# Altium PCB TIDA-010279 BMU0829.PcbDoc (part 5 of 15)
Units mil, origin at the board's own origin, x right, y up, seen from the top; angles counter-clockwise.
Board outline 11269.69 x 4438.98 mil, 4 copper layers (Top Layer, Signal Layer 1, Signal Layer 2, Bottom Layer), stack 61.6 mil thick; 1494 components, 725 nets, 3766 pads, 2728 vias.
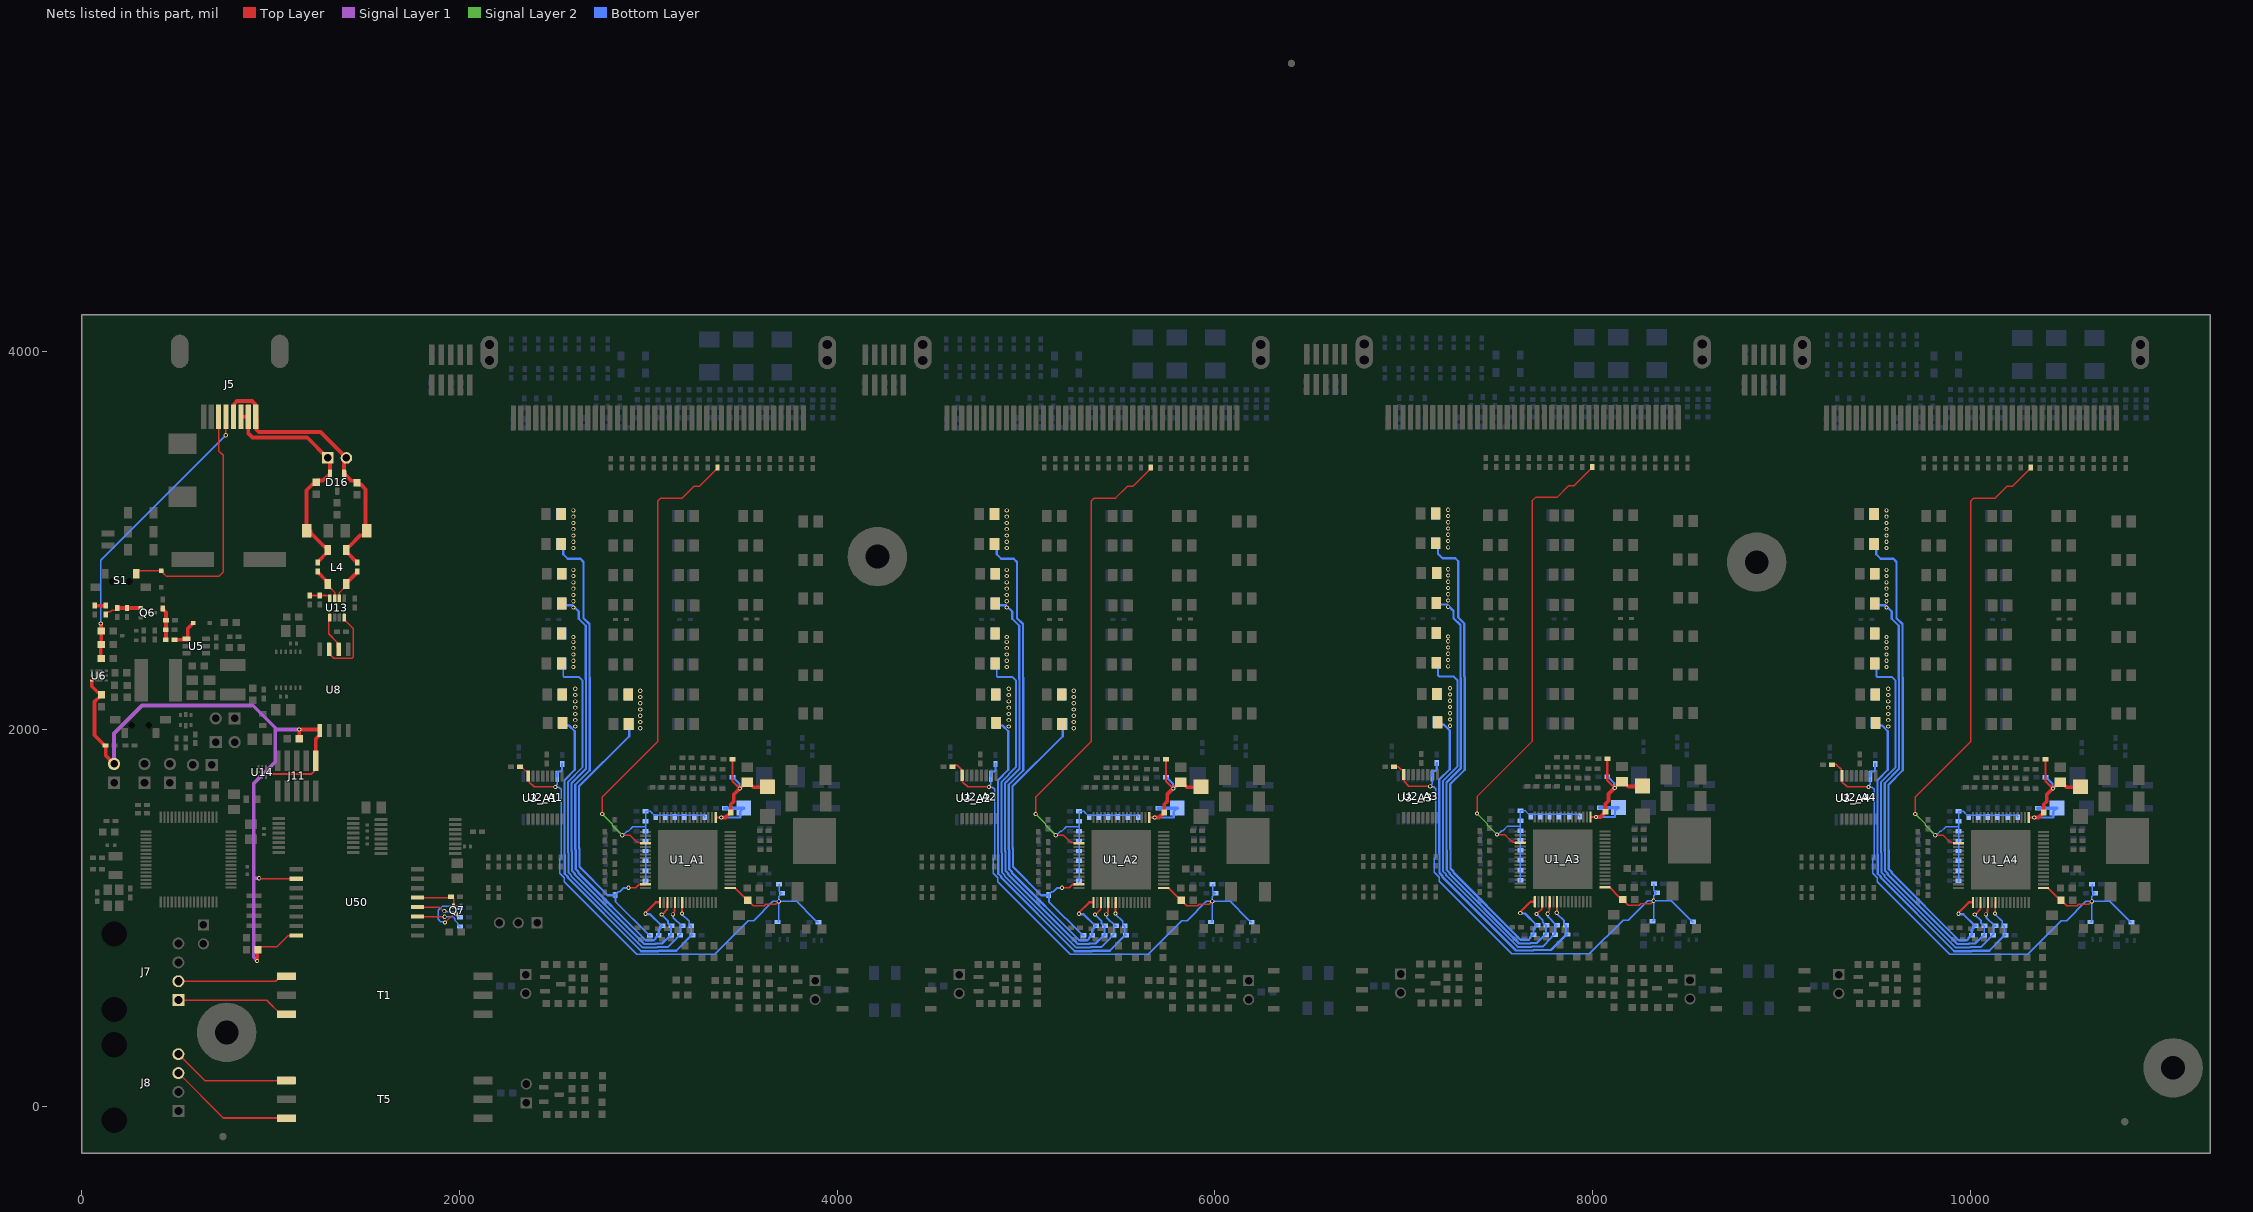
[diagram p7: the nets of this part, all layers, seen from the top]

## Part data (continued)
R144_A1 R144_A2 R144_A3 R144_A4 R147_A1 R147_A2 R147_A3 R147_A4 R152_A1 R152_A2 R152_A3 R152_A4 R156_A1 R156_A2 R156_A3 R156_A4 R158_A1 R158_A2 R158_A3 R158_A4 R162_A1 R162_A2 R162_A3 R162_A4 R208_A1 R208_A2 R208_A3 R208_A4 R209_A1 R209_A2 R209_A3 R209_A4 R210_A1 R210_A2 R210_A3 R210_A4 R211_A1 R211_A2 R211_A3 R211_A4 R212_A1 R212_A2 R212_A3 R212_A4 R213_A1 R213_A2 R213_A3 R213_A4 R214_A1 R214_A2 R214_A3 R214_A4 R216_A1 R216_A2 R216_A3 R216_A4 R217_A1 R217_A2 R217_A3 R217_A4 R218_A1 R218_A2 R218_A3 R218_A4 R219_A1 R219_A2 R219_A3 R219_A4 R220_A1 R220_A2 R220_A3 R220_A4 R221_A1 R221_A2 R221_A3 R221_A4 R222_A1 R222_A2 R222_A3 R222_A4 R223_A1 R223_A2 R223_A3 R223_A4 R224_A1 R224_A2 R224_A3 R224_A4: library part CMP-0025958-3, "RES, 10.0 k, 1%, 0.063 W, AEC-Q200 Grade 0, 0402", Manufacturer=Vishay-Dale, Power_W=63mW, Supplier Part Number 1=541-10.0KLCT-ND, TempCo="100 ppm/C", Tolerance_%=1%, Value2=0.063W, Value_Code=10k0, ValueDisplayed=10.0k
R145_A1 R145_A2 R145_A3 R145_A4 R148_A1 R148_A2 R148_A3 R148_A4 R149_A1 R149_A2 R149_A3 R149_A4 R150_A1 R150_A2 R150_A3 R150_A4 R151_A1 R151_A2 R151_A3 R151_A4 R153_A1 R153_A2 R153_A3 R153_A4 R157_A1 R157_A2 R157_A3 R157_A4 R159_A1 R159_A2 R159_A3 R159_A4 R164_A1 R164_A2 R164_A3 R164_A4 R165_A1 R165_A2 R165_A3 R165_A4 R240 R241: library part CMP-0026852-3, "RES, 1.0 k, 5%, 0.063 W, AEC-Q200 Grade 0, 0402", Manufacturer=Vishay-Dale, Power_W=63mW, Supplier Part Number 1=541-1.0KJCT-ND, TempCo="200 ppm/C", Tolerance_%=5%, Value2=0.063W, Value_Code=1k00, ValueDisplayed=1.0k
R154_A1 R154_A2 R154_A3 R154_A4: library part CMP-0016209-3, "RES, 100, 1%, 0.75 W, AEC-Q200 Grade 0, 2010", Manufacturer=Vishay-Dale, Power_W=750mW, Supplier Part Number 1=541-100ACCT-ND, TempCo="100 ppm/C", Tolerance_%=1%, Value2=0.75W, Value_Code=100R, ValueDisplayed=100
R155_A1 R155_A2 R155_A3 R155_A4: library part CMP-0016302-3, "RES, 200, 1%, 0.75 W, AEC-Q200 Grade 0, 2010", Manufacturer=Vishay-Dale, Power_W=750mW, Supplier Part Number 1=541-200ACCT-ND, TempCo="100 ppm/C", Tolerance_%=1%, Value2=0.75W, Value_Code=200R, ValueDisplayed=200
R177_A1 R177_A2 R177_A3 R177_A4 R182_A1 R182_A2 R182_A3 R182_A4 R190_A1 R190_A2 R190_A3 R190_A4 R195_A1 R195_A2 R195_A3 R195_A4: library part CMP-0025885-5, "RES, 0, 5%, 0.1 W, 0603", Manufacturer=Yageo, Power_W=100mW, Supplier Part Number 1=311-0.0GRCT-ND, TempCo="200 ppm/C", Tolerance_%=5%, Value2=0.1W, Value_Code=0000, ValueDisplayed=0
R178_A1 R178_A2 R178_A3 R178_A4 R181_A1 R181_A2 R181_A3 R181_A4 R191_A1 R191_A2 R191_A3 R191_A4 R194_A1 R194_A2 R194_A3 R194_A4: library part CMP-0025825-4, "RES, 51, 5%, 0.1 W, AEC-Q200 Grade 0, 0603", Manufacturer=Vishay-Dale, Power_W=100mW, Supplier Part Number 1=541-51GCT-ND, TempCo="200 ppm/C", Tolerance_%=5%, Value2=0.1W, Value_Code=51R0, ValueDisplayed=51
R179_A1 R179_A2 R179_A3 R179_A4 R180_A1 R180_A2 R180_A3 R180_A4 R192_A1 R192_A2 R192_A3 R192_A4 R193_A1 R193_A2 R193_A3 R193_A4: library part CMP-0025874-4, "RES, 0, 5%, 0.1 W, AEC-Q200 Grade 0, 0603", Manufacturer=Panasonic, Power_W=100mW, Supplier Part Number 1=P0.0GCT-ND, TempCo="600 ppm/C", Tolerance_%=5%, Value2=0.1W, Value_Code=0000, ValueDisplayed=0
R184_A1 R184_A2 R184_A3 R184_A4 R185_A1 R185_A2 R185_A3 R185_A4 R188_A1 R188_A2 R188_A3 R188_A4 R189_A1 R189_A2 R189_A3 R189_A4: library part CMP-0025823-4, "RES, 510, 5%, 0.1 W, AEC-Q200 Grade 0, 0603", Manufacturer=Vishay-Dale, Power_W=100mW, Supplier Part Number 1=541-510GCT-ND, TempCo="200 ppm/C", Tolerance_%=5%, Value2=0.1W, Value_Code=510R, ValueDisplayed=510
R186_A1 R186_A2 R186_A3 R186_A4 R187_A1 R187_A2 R187_A3 R187_A4: library part CMP-0022680-4, "RES, 1.00 k, 1%, 0.1 W, 0603", Manufacturer=Panasonic, Power_W=100mW, Supplier Part Number 1=P1.00KHCT-ND, TempCo="100 ppm/C", Tolerance_%=1%, Value2=0.1W, Value_Code=1k00, ValueDisplayed=1.00k
R214: library part CMP-0026935-3, "RES, 47 k, 5%, 0.063 W, AEC-Q200 Grade 0, 0402", Manufacturer=Vishay-Dale, Power_W=63mW, Supplier Part Number 1=541-47KJCT-ND, TempCo="200 ppm/C", Tolerance_%=5%, Value2=0.063W, Value_Code=47k0, ValueDisplayed=47k
R215_A1 R215_A2 R215_A3 R215_A4 R257_A1 R257_A2 R257_A3 R257_A4: library part CMP-0025950-3, "RES, 100 k, 1%, 0.063 W, AEC-Q200 Grade 0, 0402", Manufacturer=Vishay-Dale, Power_W=63mW, Supplier Part Number 1=541-100KLCT-ND, TempCo="100 ppm/C", Tolerance_%=1%, Value2=0.063W, Value_Code=100k
R218: library part CMP-0025973-3, "RES, 118 k, 1%, 0.063 W, AEC-Q200 Grade 0, 0402", Manufacturer=Vishay-Dale, Power_W=63mW, Supplier Part Number 1=541-118KLCT-ND, TempCo="100 ppm/C", Tolerance_%=1%, Value2=0.063W, Value_Code=118k
R219: library part CMP-0026178-2, "RES, 22.1 k, 1%, 0.063 W, AEC-Q200 Grade 0, 0402", Manufacturer=Vishay-Dale, Power_W=63mW, Supplier Part Number 1=541-22.1KLCT-ND, TempCo="100 ppm/C", Tolerance_%=1%, Value2=0.063W, Value_Code=22k1, ValueDisplayed=22.1k
R220 R237 R238: library part CMP-0025697-4, "RES, 0, 5%, 0.1 W, AEC-Q200 Grade 0, 0603", Manufacturer=Vishay-Dale, Power_W=100mW, Supplier Part Number 1=541-0.0GCT-ND, TempCo="200 ppm/C", Tolerance_%=5%, Value2=0.1W, Value_Code=0000, ValueDisplayed=0
R223: library part CMP-0025885-5, "RES, 0, 5%, 0.1 W, 0603", Manufacturer=Yageo, Power_W=100mW, Supplier Part Number 1=311-0.0GRCT-ND, TempCo="200 ppm/C", Tolerance_%=5%, Value2=0.1W, Value_Code=0000, ValueDisplayed=DNC
R226: library part CMP-0026878-3, "RES, 220, 5%, 0.063 W, AEC-Q200 Grade 0, 0402", Manufacturer=Vishay-Dale, Power_W=63mW, Supplier Part Number 1=541-220JCT-ND, TempCo="200 ppm/C", Tolerance_%=5%, Value2=0.063W, Value_Code=220R, ValueDisplayed=220
R227 R228: library part CMP-0026906-3, "RES, 330, 5%, 0.063 W, AEC-Q200 Grade 0, 0402", Manufacturer=Vishay-Dale, Power_W=63mW, Supplier Part Number 1=541-330JCT-ND, TempCo="200 ppm/C", Tolerance_%=5%, Value2=0.063W, Value_Code=330R, ValueDisplayed=330
R229: library part CMP-0088648-1, "Res Thin Film 0402 100K Ohm 0.1% 1/16W ±25ppm/°C Molded SMD SMD Punched Carrier T/R", Digikey Part Number=P100KDCCT-ND, Manufacturer=Panasonic, Mouser Part Number=667-ERA-2AEB104X, Octopart Part Number=aea26725a1f47165, Operating Temperature Range="-55°C to +155°C", Power_W=63mW, TempCo=25ppm/°C, Tolerance_%=0.1%, Voltage=25V
R230 R231 R232: library part CMP-0025701-4, "RES, 10 k, 5%, 0.1 W, AEC-Q200 Grade 0, 0603", Manufacturer=Vishay-Dale, Power_W=100mW, Supplier Part Number 1=541-10KGCT-ND, TempCo="200 ppm/C", Tolerance_%=5%, Value2=0.1W, Value_Code=10k0, ValueDisplayed=10k
R233 R234 R244 R258: library part CMP-0026825-5, "RES, 10 k, 5%, 0.063 W, AEC-Q200 Grade 0, 0402", Manufacturer=Vishay-Dale, Power_W=63mW, Supplier Part Number 1=541-10KJCT-ND, TempCo="200 ppm/C", Tolerance_%=5%, Value2=0.063W, Value_Code=10k0, ValueDisplayed=10k
R236: library part CMP-0026823-3, "RES, 100 k, 5%, 0.063 W, AEC-Q200 Grade 0, 0402", Manufacturer=Vishay-Dale, Power_W=63mW, Supplier Part Number 1=541-100KJCT-ND, TempCo="200 ppm/C", Tolerance_%=5%, Value2=0.063W, Value_Code=100k
R246 R247: library part CMP-0022097-4, "RES, 18.2 k, 1%, 0.1 W, AEC-Q200 Grade 0, 0603", Manufacturer=Vishay-Dale, Power_W=100mW, Supplier Part Number 1=541-18.2KHCT-ND, TempCo="100 ppm/C", Tolerance_%=1%, Value2=0.1W, Value_Code=18k2, ValueDisplayed=18.2k
R249 R252: library part CMP-0017672-3, "RES, 60.4, 1%, 0.25 W, AEC-Q200 Grade 0, 1206", Manufacturer=Panasonic, Power_W=250mW, Supplier Part Number 1=P60.4FCT-ND, TempCo="100 ppm/C", Tolerance_%=1%, Value2=0.25W, Value_Code=60R4, ValueDisplayed=60.4
R255 R256: library part CMP-0026681-1, "RES, 2.20 k, 1%, 0.1 W, 0402", Manufacturer=Panasonic, Power_W=100mW, Supplier Part Number 1=P2.20KLCT-ND, TempCo="100 ppm/C", Tolerance_%=1%, Value2=0.1W, Value_Code=2k20, ValueDisplayed=2.20k
RT1_A1 RT1_A2 RT1_A3 RT1_A4 RT2_A1 RT2_A2 RT2_A3 RT2_A4 RT3_A1 RT3_A2 RT3_A3 RT3_A4 RT4_A1 RT4_A2 RT4_A3 RT4_A4: library part CMP-0091865-2, "±1% tolerance 10kΩ linear thermistor available in 0402 and 0603 package options 2-SOT-5X3 -40 to 125", Digikey Part Number=296-TMP6131DYATCT-ND, Manufacturer="Texas Instruments", Max Current=400uA, Mouser Part Number=595-TMP6131DYAT, Operating Temperature Range="-40°C to +125°C", TempCo=6400ppm/°C, Tolerance_%=1%
S1 S2: library part CMP-0002328-1, "Switch, SPST, 0.05 A, 12 VDC, SMD", CurrentRating_mA=50A, Manufacturer=Diptronics
T1 T5: library part CMP-0122349-1, "SMD BMS Transformer", Manufacturer="LineKey Technology", Operating Temperature Range="-40°C to +125°C", Voltage_Isolation_Vrms=5000VDC
T2 T3 T4: library part CMP-0086619-1, "BMS TRANSFORMER", Manufacturer="Wurth Elektronik"
U1_A1 U1_A2 U1_A3 U1_A4: library part CMP-0122614-1, "Functional Safety-Compliant 14S Battery Monitor", Manufacturer="Texas Instruments", Max Supply Voltage=70V, Min Supply Voltage=9V, Nominal Supply Current=3.5mA, Operating Temperature Range="-40°C to +150°C"
U2_A1 U2_A2 U2_A3 U2_A4 U3_A1 U3_A2 U3_A3 U3_A4: library part CMP-0090991-1, "5-V, 8: 1, 1-channel general-purpose multiplexer with 1.8-V logic control 16-TSSOP -40 to 125", Digikey Part Number=296-TMUX1308PWRCT-ND, Manufacturer="Texas Instruments", Max Supply Voltage=5.5V, Min Supply Voltage=1.62V, Mouser Part Number=595-TMUX1308PWR, Nominal Supply Current=1uA, On State Resistance=75-650Ω, Operating Temperature Range="-40°C to +125°C"
U5: library part CMP-0121877-1, "SIMPLE SWITCHER® Power Converter, 4-V to 42-V, 1-A Buck Converter, SOT23", Manufacturer="Texas Instruments", Max Supply Voltage=42V, Min Supply Voltage=4V, Nominal Supply Current=26.5-420uA, Operating Temperature Range="-40°C to +150°C", Output Voltage=0.8-28V, PartNumber=LMR51406YDBVR, Switching Frequency=1.1MHz
U6: library part CMP-0860463-2, "Automotive 150-mA high-voltage ultra-low-IQ low-dropout (LDO) linear regulator, DRV0006A (WSON-6)", Alternate Manufacturer="Texas Instruments", Operating Temperature Range="-40 to 150 C", Rating=Automotive
U7: library part CMP-0098322-4, "1.5W, High-Density, >3 kVRMS Isolated DC-DC Converter", Manufacturer="Texas Instruments", Max Supply Voltage=5.5V, Min Supply Voltage=4.5V, Operating Temperature Range=to, Output Voltage=5V
U8: library part CMP-0094881-1, "General Purpose Reinforced and Basic Dual-Channel Automotive Digital Isolators with Robust EMC", Manufacturer="Texas Instruments", Max Supply Voltage=5.5V, Min Supply Voltage=1.71V, Operating Temperature Range="-40°C to +125°C"
U9 U10: library part CMP-0120108-2, "1.5W, High-Density, >5 kVRMS Isolated DC-DC Converter", Manufacturer="Texas Instruments", Max Supply Voltage=5.5V, Min Supply Voltage=4.5V, Operating Temperature Range="-40°C to +125°C", Output Voltage=5/5.5V
U13: library part CMP-0089901-1, "Automotive High Speed CAN Transceiver", Manufacturer="Texas Instruments", Max Supply Voltage=5.5V, Min Supply Voltage=4.5V, Nominal Supply Current=5-180mA, Operating Temperature Range="-40°C to +150°C"
U14: library part CMP-0043125-4, "Low-Capacitance 6-Channel +/-15 kV ESD Protection Array for High-Speed Data Interfaces, RSE0008A (UQFN-8)", Breakdown Voltage(Min)(V)=6, IO Capacitance(Typ)(pF)=1.6, IO Leakage Current(nA)=1, Manufacturer="Texas Instruments"
U50: "Automotive, robust EMC, quad-channel, 3/1, reinforced digital isolator 16-SOIC -40 to 125", Manufacturer_Name="Texas Instruments", Manufacturer_Part_Number=ISO7741FQDWWQ1
Y1: library part CMP-2000-05089-1, "Turning Fork Crystal Unit, 32.768 KHz, -40 to 85 degC, 2-Pin SMD, RoHS, Tape and Reel", Manufacturer="Citizen Micro HumanTech", Package Description="2-Pin Surface Mount Device, Body 1.6 x 3.3 mm, Pitch 2.5 mm", Package Reference=CM315D-2, Package Version="Rev. 1.4, 09/2012"
Y2: library part CMP-0098168-2, "Crystal 40MHz ±10ppm (Tol) ±20ppm (Stability) 12pF FUND 40Ohm 4-Pin Mini-CSMD T/R", Frequency Stability=20ppm, Frequency Tolerance=10ppm, Frequency_Fixed=40MHz, Load Capacitance=12pF, Manufacturer="Seiko Epson", Operating Temperature Range="-40°C to +105°C"
ZZ1: library part CMP-0003616-3
ZZ2: library part CMP-0077236-1
ZZ3: library part CMP-0077237-1
ZZ4: library part CMP-0077238-1

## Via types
v1: diameter 22.01, hole 12.01, Top Layer to Bottom Layer, tented both sides, 2578 vias
v2: diameter 19.68, hole 7.87, Top Layer to Bottom Layer, tented both sides, 144 vias
v3: diameter 92.52, hole 49.21, Top Layer to Bottom Layer, 4 vias
v4: diameter 19.68, hole 7.87, Top Layer to Bottom Layer, 2 vias

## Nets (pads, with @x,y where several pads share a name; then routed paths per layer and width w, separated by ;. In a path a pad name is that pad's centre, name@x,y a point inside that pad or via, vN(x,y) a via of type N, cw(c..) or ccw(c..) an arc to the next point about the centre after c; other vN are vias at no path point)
3V3: C198.1 C201.2 C216.1 J9.2 J11.1 R214.2 U6.6 U8.1 U14.8 U50.10 U50.16 | length 4152.9
  Top Layer w8: v1@943.11,1210.63 946.07,1207.68 U50.10@1135.69,1207.68 ; C216.1@944.88,846.46 945.65,847.23 1034.23,847.23 1092.88,905.87 1133.89,905.87 U50.16@1135.69,907.68 ; J11.1@1238.86,1831.81 J11.1@1238.86,1866.69
  Top Layer w10: U14.8@982.2,1772.82 988.1,1772.82 989.01,1771.91 989.01,1767.37 994.86,1761.51 1216.22,1761.51 1229.29,1774.58 1229.29,1781.89 1231.55,1784.15 J11.1@1238.86,1784.15
  Top Layer w15: v1(928.97,772.08) 930.31,773.42 930.31,828.09 C216.1@933.76,831.54
  Top Layer w20: U6.6@52.79,2257.6 52.79,2227.26 C198.1@93.2,2186.86 ; C198.1@104.46,2181.17 104.46,2180.18 80.01,2155.74 78.36,2155.74 67.89,2145.27 67.89,1967.42 122.17,1913.14 R214.2@126.11,1913.14 127.61,1911.63 127.61,1860.41 171.17,1816.85 J9.2@171.17,1815.6 ; C201.2@1151.78,1948.73 v1(1151.78,1998.22) U8.1@1258.39,1998.22 ; J11.1@1238.86,1866.69 1238.7,1866.85 1238.86,1867.01 1238.86,1947.81 1260.2,1969.16 U8.1@1260.2,1992.78
  Signal Layer 1 w20: J9.2@171.17,1815.6 171.17,1976.93 319.62,2125.38 895.67,2125.38 ; 895.67,2125.98 905.51,2125.98 1024.62,2006.88 ; v1@925.2,777.56 910.53,792.23 910.53,1210.63 ; v1@935.04,1210.63 910.53,1210.63 ; v1(1151.78,1998.22) 1033.28,1998.22 1024.62,2006.88 ; 910.53,1210.63 910.53,1711.61 1024.62,1825.7 1024.62,2006.88
  other v1: 939.4,1210.55
AFE_FLT: R210.2 U50.3 | length 258.6
  Top Layer w8: U50.3@1777.69,1007.68 1920.07,1007.68 v1(1921.54,1006.21)
  Bottom Layer w8: v1(1921.54,1006.21) 1966.23,1006.21 1976.31,996.13 1976.31,987.21 1992.19,971.33 1992.19,962.54 2000,954.72 R210.2@2003.94,954.72
AFE_RX: Q7.3 R208.2 | length 304.3
  Top Layer w8: v1(1923.2,976.38) 1924.06,976.38 1967.76,1020.08 Q7.3@1988.58,1020.08
  Bottom Layer w8: v1(1923.2,976.38) 1920.52,979.06 1900.83,979.06 1887.22,992.67 1887.22,1040.77 1909.45,1062.99 1990.16,1062.99 2000,1053.15 R208.2@2003.94,1053.15
AFE_RX_R: Q7.2 R258.1 U50.5 | length 237.3
  Top Layer w8: U50.5@1777.69,1107.68 1950.2,1107.68 R258.1@1954.72,1112.2 1962.54,1104.39 1968.5,1104.39 Q7.2@1968.5,1062.99
AFE_TX: R209.2 U50.4 | length 244.8
  Top Layer w8: U50.4@1777.69,1057.68 1894.53,1057.68 1918.74,1033.46 v1@1919.29,1033.46 ; v1@1919.29,1036.05 v1(1919.94,1036.05)
  Bottom Layer w8: v1(1919.94,1036.05) 1922.62,1033.37 1968.6,1033.37 1990.22,1011.75 1992.19,1011.75 1998.03,1005.91 R209.2@1998.03,1003.94
AVDD_A1: C55_A1.2 C120_A1.1 C140_A1.1 R121_A1.2 R122_A1.2 R215_A1.2 R257_A1.2 U1_A1.49 U2_A1.16 U3_A1.16 | length 3100.1
  Top Layer w7: U2_A1.16@2363.95,1752.49 2369.31,1747.13 2369.31,1719.39 2395.07,1693.63 v1(2507.8,1693.63) ; U1_A1.49@3433.88,1159.32 3457.5,1159.32 3509.29,1107.53 3513.65,1107.53 C55_A1.2@3527.35,1093.83 3528.34,1093.83 3556.74,1065.42 3564.28,1065.42 3565.95,1063.75 3614.74,1063.75 3622.68,1071.7 3674.79,1071.7 v1(3690.91,1087.81)
  Top Layer w8: C120_A1.1@2322.83,1801.18 2326.77,1801.18 2349.93,1778.02 2359.09,1778.02 2362.2,1774.9 U2_A1.16@2362.2,1771.65
  Bottom Layer w7: v1@2510.4,1695.09 2514.73,1690.76 2526.84,1690.76 2531.73,1685.87 2532.77,1685.87 2537.72,1680.92 2537.72,1318.65 2529.83,1310.76 2529.83,1238 2555.68,1212.15 2555.68,1190.65 2939.33,807.01 3350.46,807.01 3528.96,985.51 3557.16,985.51 3659.47,1087.81 v1(3690.91,1087.81) ; v1@2510.4,1700.29 2517.49,1707.38 U3_A1.16@2517.49,1748.54 ; R121_A1.2@3684.47,978.59 3690.91,985.03 v1(3690.91,1087.81) ; R215_A1.2@3692.39,1177.81 3692.39,1142.75 R257_A1.2@3704.15,1130.99 ; R257_A1.2@3708.09,1130.99 R257_A1.2@3704.15,1130.99 ; R122_A1.2@3899.74,977.11 3895.8,977.11 3879.61,993.29 3879.61,993.63 3785.43,1087.81 v1(3690.91,1087.81) ; v1(3690.91,1087.81) 3690.91,1113.81 3695.84,1118.74 3695.84,1122.68 R257_A1.2@3704.15,1130.99
  Bottom Layer w12: U3_A1.16@2517.49,1748.54 2517.49,1769.21 2523.52,1775.24 2536,1775.24 2543.08,1782.33 C140_A1.1@2543.08,1816.08
AVDD_A2: C55_A2.2 C120_A2.1 C140_A2.1 R121_A2.2 R122_A2.2 R215_A2.2 R257_A2.2 U1_A2.49 U2_A2.16 U3_A2.16 | length 3143.6
  Top Layer w7: C120_A2.1@4610.24,1801.18 4618.55,1809.49 4634.52,1809.49 4656.19,1787.82 4656.19,1766.23 4661.48,1760.95 4658.96,1758.43 4664.32,1753.08 4664.32,1719.39 4690.09,1693.63 v1(4802.82,1693.63) ; U1_A2.49@5728.89,1159.32 5752.51,1159.32 5804.31,1107.53 5808.67,1107.53 C55_A2.2@5822.37,1093.83 5823.35,1093.83 5851.76,1065.42 5859.29,1065.42 5860.96,1063.75 5909.76,1063.75 5917.7,1071.7 5969.81,1071.7 v1(5985.92,1087.81)
  Bottom Layer w7: v1@4805.42,1695.09 4809.75,1690.76 4821.86,1690.76 4826.75,1685.87 4827.79,1685.87 4832.74,1680.92 4832.74,1318.65 4824.85,1310.76 4824.85,1238 4850.7,1212.15 4850.7,1190.65 5234.34,807.01 5645.48,807.01 5823.97,985.51 5852.18,985.51 5954.48,1087.81 v1(5985.92,1087.81) ; v1@4805.42,1700.29 4812.51,1707.38 U3_A2.16@4812.51,1748.54 ; R121_A2.2@5979.48,978.59 5985.92,985.03 v1(5985.92,1087.81) ; R215_A2.2@5987.4,1177.81 5987.4,1142.75 R257_A2.2@5999.17,1130.99 ; R257_A2.2@6003.1,1130.99 R257_A2.2@5999.17,1130.99 ; R122_A2.2@6194.75,977.11 6190.81,977.11 6174.63,993.29 6174.63,993.63 6080.45,1087.81 v1(5985.92,1087.81) ; v1(5985.92,1087.81) 5985.92,1113.81 5990.86,1118.74 5990.86,1122.68 R257_A2.2@5999.17,1130.99
  Bottom Layer w12: U3_A2.16@4812.51,1748.54 4812.51,1769.21 4818.54,1775.24 4831.02,1775.24 4838.1,1782.33 C140_A2.1@4838.1,1816.08
AVDD_A3: C55_A3.2 C120_A3.1 C140_A3.1 R121_A3.2 R122_A3.2 R215_A3.2 R257_A3.2 U1_A3.49 U2_A3.16 U3_A3.16 | length 3128
  Top Layer w7: C120_A3.1@6948.82,1801.18 6950.41,1799.59 6970.97,1799.59 6986.06,1784.5 6993.64,1784.5 6998.99,1779.15 U2_A3.16@6998.99,1759.35 7000.92,1757.42 7000.92,1722.6 7026.68,1696.84 v1(7139.41,1696.84) ; U1_A3.49@8065.49,1162.53 8089.11,1162.53 8140.9,1110.74 8145.26,1110.74 C55_A3.2@8158.96,1097.03 8159.95,1097.03 8188.35,1068.63 8195.89,1068.63 8197.56,1066.96 8246.35,1066.96 8254.3,1074.9 8306.41,1074.9 v1(8322.52,1091.02)
  Bottom Layer w7: v1@7142.01,1698.3 7146.35,1693.97 7158.46,1693.97 7163.34,1689.08 7164.39,1689.08 7169.34,1684.13 7169.34,1321.86 7161.45,1313.97 7161.45,1241.21 7187.3,1215.36 7187.3,1193.86 7570.94,810.22 7982.08,810.22 8160.57,988.71 8188.78,988.71 8291.08,1091.02 v1(8322.52,1091.02) ; v1@7142.01,1703.5 7149.1,1710.59 U3_A3.16@7149.1,1751.75 ; R121_A3.2@8316.08,981.79 8322.52,988.24 v1(8322.52,1091.02) ; R215_A3.2@8324,1181.02 8324,1145.96 R257_A3.2@8335.76,1134.2 ; R257_A3.2@8339.7,1134.2 R257_A3.2@8335.76,1134.2 ; R122_A3.2@8531.35,980.32 8527.41,980.32 8511.23,996.5 8511.23,996.84 8417.05,1091.02 v1(8322.52,1091.02) ; v1(8322.52,1091.02) 8322.52,1117.02 8327.45,1121.95 8327.45,1125.89 R257_A3.2@8335.76,1134.2
  Bottom Layer w12: U3_A3.16@7149.1,1751.75 7149.1,1772.42 7155.14,1778.45 7167.61,1778.45 7174.69,1785.54 C140_A3.1@7174.69,1819.28
AVDD_A4: C55_A4.2 C120_A4.1 C140_A4.1 R121_A4.2 R122_A4.2 R215_A4.2 R257_A4.2 U1_A4.49 U2_A4.16 U3_A4.16 | length 3143.7
  Top Layer w7: C120_A4.1@9265.75,1811.02 9269.19,1814.47 9287.9,1814.47 9314.78,1787.59 9314.78,1758.25 9321.15,1751.88 9321.15,1719.39 9346.91,1693.63 v1(9459.64,1693.63) ; U1_A4.49@10385.72,1159.32 10409.34,1159.32 10461.13,1107.53 10465.49,1107.53 C55_A4.2@10479.19,1093.83 10480.18,1093.83 10508.58,1065.42 10516.12,1065.42 10517.79,1063.75 10566.58,1063.75 10574.53,1071.7 10626.64,1071.7 v1(10642.75,1087.81)
  Bottom Layer w7: v1@9462.24,1695.09 9466.58,1690.76 9478.69,1690.76 9483.57,1685.87 9484.62,1685.87 9489.57,1680.92 9489.57,1318.65 9481.68,1310.76 9481.68,1238 9507.53,1212.15 9507.53,1190.65 9891.17,807.01 10302.3,807.01 10480.8,985.51 10509.01,985.51 10611.31,1087.81 v1(10642.75,1087.81) ; v1@9462.24,1700.29 9469.33,1707.38 U3_A4.16@9469.33,1748.54 ; R121_A4.2@10636.31,978.59 10642.75,985.03 v1(10642.75,1087.81) ; R215_A4.2@10644.23,1177.81 10644.23,1142.75 R257_A4.2@10655.99,1130.99 ; R257_A4.2@10659.93,1130.99 R257_A4.2@10655.99,1130.99 ; R122_A4.2@10851.58,977.11 10847.64,977.11 10831.46,993.29 10831.46,993.63 10737.28,1087.81 v1(10642.75,1087.81) ; v1(10642.75,1087.81) 10642.75,1113.81 10647.68,1118.74 10647.68,1122.68 R257_A4.2@10655.99,1130.99
  Bottom Layer w12: U3_A4.16@9469.33,1748.54 9469.33,1769.21 9475.37,1775.24 9487.84,1775.24 9494.92,1782.33 C140_A4.1@9494.92,1816.08
BAT_A1: C1_A1.2 C26_A1.2 D1_A1.1 D9_A1.1 R36_A1.2 R204_A1.1 R207_A1.1 U1_A1.1 | length 966.4
  Top Layer w10: U1_A1.1@3357.11,1531.37 v1@3381.76,1531.37
  Top Layer w12: v1@3381.76,1531.37 v1@3385.83,1535.43 ; R207_A1.1@3446.1,1839.56 3445.44,1838.9 3445.44,1724.1 v1(3484.68,1684.86) 3488.65,1688.83 3488.65,1690.41 R36_A1.2@3517.1,1718.86
  Top Layer w20: v1@3385.83,1531.37 3409.05,1531.37 C26_A1.2@3436.28,1558.6 3436.28,1601.73 3451.84,1617.29 3451.84,1653.6 3517.1,1718.86 R36_A1.2@3523.6,1718.86 3530.1,1718.86 3556.68,1692.28 3628.83,1692.28 D9_A1.1@3631.54,1694.99
  Bottom Layer w12: v1(3385.62,1531.37) 3486.85,1531.37 3486.85,1563.81 3503.63,1580.59 D1_A1.1@3505.26,1582.22 ; C1_A1.2@3445.26,1744.01 3449.2,1744.01 3482.77,1710.44 3482.77,1686.77 v1(3484.68,1684.86)
  Bottom Layer w20: R204_A1.1@3405.8,1580.59 D1_A1.1@3503.63,1580.59
BAT_A2: C1_A2.2 C26_A2.2 D1_A2.1 D9_A2.1 R36_A2.2 R204_A2.1 R207_A2.1 U1_A2.1 | length 966.4
  Top Layer w10: U1_A2.1@5652.12,1531.37 v1@5676.77,1531.37
  Top Layer w12: v1@5676.77,1531.37 v1@5680.84,1535.43 ; R207_A2.1@5741.12,1839.56 5740.45,1838.9 5740.45,1724.1 v1(5779.7,1684.86) 5783.67,1688.83 5783.67,1690.41 R36_A2.2@5812.12,1718.86
  Top Layer w20: v1@5680.84,1531.37 5704.07,1531.37 C26_A2.2@5731.3,1558.6 5731.3,1601.73 5746.86,1617.29 5746.86,1653.6 5812.12,1718.86 R36_A2.2@5818.62,1718.86 5825.12,1718.86 5851.69,1692.28 5923.84,1692.28 D9_A2.1@5926.55,1694.99
  Bottom Layer w12: v1(5680.64,1531.37) 5781.86,1531.37 5781.86,1563.81 5798.64,1580.59 D1_A2.1@5800.28,1582.22 ; C1_A2.2@5740.28,1744.01 5744.21,1744.01 5777.78,1710.44 5777.78,1686.77 v1(5779.7,1684.86)
  Bottom Layer w20: R204_A2.1@5700.82,1580.59 D1_A2.1@5798.64,1580.59
BAT_A3: C1_A3.2 C26_A3.2 D1_A3.1 D9_A3.1 R36_A3.2 R204_A3.1 R207_A3.1 U1_A3.1 | length 966.4
  Top Layer w10: U1_A3.1@7988.72,1534.57 v1@8013.37,1534.57
  Top Layer w12: v1@8013.37,1534.57 v1@8017.44,1538.64 ; R207_A3.1@8077.72,1842.77 8077.05,1842.1 8077.05,1727.31 v1(8116.3,1688.07) 8120.26,1692.03 8120.26,1693.61 R36_A3.2@8148.72,1722.07
  Top Layer w20: v1@8017.44,1534.57 8040.66,1534.57 C26_A3.2@8067.9,1561.81 8067.9,1604.94 8083.45,1620.49 8083.45,1656.8 8148.72,1722.07 R36_A3.2@8155.22,1722.07 8161.72,1722.07 8188.29,1695.49 8260.44,1695.49 D9_A3.1@8263.14,1698.2
  Bottom Layer w12: v1(8017.24,1534.57) 8118.46,1534.57 8118.46,1567.02 8135.24,1583.79 D1_A3.1@8136.88,1585.42 ; C1_A3.2@8076.87,1747.22 8080.81,1747.22 8114.38,1713.65 8114.38,1689.98 v1(8116.3,1688.07)
  Bottom Layer w20: R204_A3.1@8037.42,1583.79 D1_A3.1@8135.24,1583.79
BAT_A4: C1_A4.2 C26_A4.2 D1_A4.1 D9_A4.1 R36_A4.2 R204_A4.1 R207_A4.1 U1_A4.1 | length 966.4
  Top Layer w10: U1_A4.1@10308.95,1531.37 v1@10333.6,1531.37
  Top Layer w12: v1@10333.6,1531.37 v1@10337.67,1535.43 ; R207_A4.1@10397.94,1839.56 10397.28,1838.9 10397.28,1724.1 v1(10436.53,1684.86) 10440.49,1688.83 10440.49,1690.41 R36_A4.2@10468.95,1718.86
  Top Layer w20: v1@10337.67,1531.37 10360.89,1531.37 C26_A4.2@10388.12,1558.6 10388.12,1601.73 10403.68,1617.29 10403.68,1653.6 10468.95,1718.86 R36_A4.2@10475.45,1718.86 10481.95,1718.86 10508.52,1692.28 10580.67,1692.28 D9_A4.1@10583.37,1694.99
  Bottom Layer w12: v1(10337.47,1531.37) 10438.69,1531.37 10438.69,1563.81 10455.47,1580.59 D1_A4.1@10457.11,1582.22 ; C1_A4.2@10397.1,1744.01 10401.04,1744.01 10434.61,1710.44 10434.61,1686.77 v1(10436.53,1684.86)
  Bottom Layer w20: R204_A4.1@10357.65,1580.59 D1_A4.1@10455.47,1580.59
BB_A1: C61_A1.2 C62_A1.1 C67_A1.2 C68_A1.1 C75_A1.2 C76_A1.1 C79_A1.2 C80_A1.1 C84_A1.2 C85_A1.1 C89_A1.2 C90_A1.1 C96_A1.2 C97_A1.1 R79_A1.1 U1_A1.20 | length 3316.1
  Top Layer w8: v1(2755.69,1550.41) 2755.91,1550.62 2755.91,1640.43 3049.41,1933.94 3049.41,3207.03 3065.66,3223.29 3179.04,3223.29 3241.49,3285.73 3270.56,3285.73 3366.1,3381.28 R79_A1.1@3366.1,3385.21 ; v1(2861.72,1438.16) 2902.68,1438.16 2909.91,1430.94 2937.77,1403.07 2941.76,1403.07 2947.38,1397.44 2983.15,1397.44 U1_A1.20@2985.06,1395.54
  Signal Layer 2 w8: v1(2755.69,1550.41) 2809.28,1496.83 2809.28,1490.6 v1(2861.72,1438.16) 2862.87,1437.01 v1@2864.17,1437.01
  Bottom Layer w8: v1@2866.02,1438.16 2886.26,1458.4 2892.76,1458.4 2917.81,1483.45 2981.03,1483.45 2985.72,1488.14 ; C96_A1.2@2982.28,1190.94 2985.72,1194.38 C97_A1.1@2985.72,1249.38 C89_A1.2@2985.72,1301.98 C84_A1.2@2985.72,1407.17 C85_A1.1@2985.72,1459.77 2985.72,1488.14 ; C62_A1.1@3298.96,1533.15 3298.96,1537.09 3291.14,1544.9 3030.45,1544.9 3015.62,1559.73 3015.62,1560.27 3010.93,1564.96 C80_A1.1@2985.72,1564.96 2985.72,1488.14
BB_A2: C61_A2.2 C62_A2.1 C67_A2.2 C68_A2.1 C75_A2.2 C76_A2.1 C79_A2.2 C80_A2.1 C84_A2.2 C85_A2.1 C89_A2.2 C90_A2.1 C96_A2.2 C97_A2.1 R79_A2.1 U1_A2.20 | length 3316.1
  Top Layer w8: v1(5050.71,1550.41) 5050.92,1550.62 5050.92,1640.43 5344.43,1933.94 5344.43,3207.03 5360.68,3223.29 5474.06,3223.29 5536.51,3285.73 5565.58,3285.73 5661.12,3381.28 R79_A2.1@5661.12,3385.21 ; v1(5156.73,1438.16) 5197.7,1438.16 5204.92,1430.94 5232.79,1403.07 5236.78,1403.07 5242.4,1397.44 5278.17,1397.44 U1_A2.20@5280.07,1395.54
  Signal Layer 2 w8: v1(5050.71,1550.41) 5104.29,1496.83 5104.29,1490.6 v1(5156.73,1438.16) 5157.89,1437.01 v1@5159.19,1437.01
  Bottom Layer w8: v1@5161.04,1438.16 5181.27,1458.4 5187.77,1458.4 5212.82,1483.45 5276.05,1483.45 5280.73,1488.14 ; C96_A2.2@5277.3,1190.94 5280.73,1194.38 C97_A2.1@5280.73,1249.38 C89_A2.2@5280.73,1301.98 C84_A2.2@5280.73,1407.17 C85_A2.1@5280.73,1459.77 5280.73,1488.14 ; C62_A2.1@5593.97,1533.15 5593.97,1537.09 5586.16,1544.9 5325.47,1544.9 5310.64,1559.73 5310.64,1560.27 5305.95,1564.96 C80_A2.1@5280.73,1564.96 5280.73,1488.14
BB_A3: C61_A3.2 C62_A3.1 C67_A3.2 C68_A3.1 C75_A3.2 C76_A3.1 C79_A3.2 C80_A3.1 C84_A3.2 C85_A3.1 C89_A3.2 C90_A3.1 C96_A3.2 C97_A3.1 R79_A3.1 U1_A3.20 | length 3316.1
  Top Layer w8: v1(7387.3,1553.62) 7387.52,1553.83 7387.52,1643.64 7681.02,1937.14 7681.02,3210.24 7697.28,3226.49 7810.66,3226.49 7873.1,3288.94 7902.17,3288.94 7997.72,3384.49 R79_A3.1@7997.72,3388.42 ; v1(7493.33,1441.37) 7534.29,1441.37 7541.52,1434.14 7569.39,1406.27 7573.37,1406.27 7579,1400.65 7614.77,1400.65 U1_A3.20@7616.67,1398.75
  Signal Layer 2 w8: v1(7387.3,1553.62) 7440.89,1500.04 7440.89,1493.81 v1(7493.33,1441.37) 7494.48,1440.22 v1@7495.79,1440.22
  Bottom Layer w8: v1@7497.63,1441.37 7517.87,1461.61 7524.37,1461.61 7549.42,1486.66 7612.64,1486.66 7617.33,1491.35 ; C96_A3.2@7613.9,1194.15 7617.33,1197.59 C97_A3.1@7617.33,1252.59 C89_A3.2@7617.33,1305.18 C84_A3.2@7617.33,1410.38 C85_A3.1@7617.33,1462.97 7617.33,1491.35 ; C62_A3.1@7930.57,1536.36 7930.57,1540.3 7922.76,1548.11 7662.06,1548.11 7647.23,1562.94 7647.23,1563.48 7642.55,1568.17 C80_A3.1@7617.33,1568.17 7617.33,1491.35
BB_A4: C61_A4.2 C62_A4.1 C67_A4.2 C68_A4.1 C75_A4.2 C76_A4.1 C79_A4.2 C80_A4.1 C84_A4.2 C85_A4.1 C89_A4.2 C90_A4.1 C96_A4.2 C97_A4.1 R79_A4.1 U1_A4.20 | length 3316.1
  Top Layer w8: v1(9707.53,1550.41) 9707.75,1550.62 9707.75,1640.43 10001.25,1933.94 10001.25,3207.03 10017.51,3223.29 10130.89,3223.29 10193.33,3285.73 10222.4,3285.73 10317.95,3381.28 R79_A4.1@10317.95,3385.21 ; v1(9813.56,1438.16) 9854.52,1438.16 9861.75,1430.94 9889.62,1403.07 9893.6,1403.07 9899.23,1397.44 9935,1397.44 U1_A4.20@9936.9,1395.54
  Signal Layer 2 w8: v1(9707.53,1550.41) 9761.12,1496.83 9761.12,1490.6 v1(9813.56,1438.16) 9814.71,1437.01 v1@9816.02,1437.01
  Bottom Layer w8: v1@9817.86,1438.16 9838.1,1458.4 9844.6,1458.4 9869.65,1483.45 9932.87,1483.45 9937.56,1488.14 ; C96_A4.2@9934.13,1190.95 9937.56,1194.38 C97_A4.1@9937.56,1249.38 C89_A4.2@9937.56,1301.98 C84_A4.2@9937.56,1407.17 C85_A4.1@9937.56,1459.77 9937.56,1488.14 ; C62_A4.1@10250.8,1533.15 10250.8,1537.09 10242.99,1544.9 9982.29,1544.9 9967.46,1559.73 9967.46,1560.27 9962.78,1564.96 C80_A4.1@9937.56,1564.96 9937.56,1488.14
BMU_COMMH_N: J8.4 T5.1 | length 599.7
  Top Layer w8: J8.4@511.81,278.74 652.76,137.8 T5.1@1053.15,137.8
BMU_COMMH_P: J8.3 T5.3 | length 646.8
  Top Layer w8: J8.3@518.74,178.74 J8.3@511.81,178.74 749.61,-59.06 T5.3@1053.15,-59.06
BMU_COMML_P: J7.2 T1.1 | length 575.1
  Top Layer w8: J7.2@511.81,664.92 1027.91,664.92 1061.81,698.82 T1.1@1072.83,698.82
BMU_OMML_N: J7.1 T1.3 | length 607.7
  Top Layer w8: J7.1@537.44,590.55 J7.1@511.81,564.92 979.17,564.92 1051.97,492.13 T1.3@1053.15,492.13
BMU_WAKEIN: D14.1 R241.2 U5.4 | length 169.3
  Top Layer w20: R241.2@492.13,2473.5 U5.4@557.71,2473.5 ; U5.4@559.51,2473.5 U5.4@557.71,2473.5 ; D14.1@590.81,2561.74 561.31,2532.24 561.31,2477.1 U5.4@557.71,2473.5
BMU_WAKEIN_C: D15.2 J5.6 S1.4 | length 1338.9
  Top Layer w8: S1.4@289.37,2822.84 289.37,2825.36 303.09,2839.08 D15.2@428.12,2839.08 ; D15.2@421.01,2837.84 D15.2@425.16,2833.69 ; D15.2@428.12,2844.49 430.83,2841.78 432.27,2840.34 432.27,2825.36 449.39,2808.24 725.07,2808.24 749.05,2832.22 749.05,3449.85 724.78,3474.13 J5.6@724.78,3653.54
BMU_WAKEIN_R: C199.1 R240.2 R241.1 R244.2 | length 176.2
  Top Layer w20: R240.2@428.12,2637.8 428.12,2633.86 429.93,2632.05 433.13,2632.05 446.85,2618.33 R244.2@446.85,2576.52 446.7,2576.52 444.88,2574.71 445.87,2574.71 445.87,2474.49 R241.1@444.88,2473.5
BMU_WAKEOUT: R216.2 R235.1 | length 58.5
  Top Layer w20: R216.2@71.79,2653.48 R235.1@127.19,2653.48 ; R235.1@115.53,2653.48 117.35,2651.67 R235.1@117.35,2651.08
BMU_WAKEOUT_C: J5.2 R230.2 R231.2 R232.2 | length 1550
  Top Layer w8: v1(762.83,3556.08) 763.49,3556.74 763.49,3652.88 J5.2@764.15,3653.54
  Top Layer w20: R232.2@100.53,2379.09 R230.2@100.53,2447.34 ; v1(101.15,2559.14) 101.53,2558.76 101.53,2521.49 R231.2@103.48,2519.54 R230.2@103.48,2447.34
  Bottom Layer w8: v1(101.15,2559.14) 101.15,2894.4 v1(762.83,3556.08)
BMU_WAKEOUT_R: C196.1 Q6.1 R235.2 R236.2 | length 178.2
  Top Layer w8: 139,2621.04 151.42,2621.04 160.24,2629.86 R236.2@188.77,2629.86
  Top Layer w20: R236.2@188.77,2641.67 C196.1@239.74,2641.67 240,2641.41 312,2641.41 Q6.1@312.27,2641.14 Q6.1@311.2,2641.14
CAN0_CANH: C218.1 D16.2 J5.3 J5.8 J21.1 L4.4 R248.2 R249.2 | length 1339.8
  Top Layer w8: J5.3@842.89,3602.36 J5.3@842.89,3653.54
  Top Layer w20: J5.3@842.89,3653.54 J5.8@882.26,3653.54 882.26,3565.19 904.14,3543.31 1193.83,3543.31 J21.1@1301.61,3435.53 1314.57,3422.57 1314.57,3345.98 1312.76,3344.17 1304.88,3344.17 1276.46,3315.75 1250.51,3315.75 1241.81,3307.05 C218.1@1241.81,3306.06 ; R249.2@1190.7,3050.2 1190.7,3264.47 1222.6,3296.38 C218.1@1233.11,3296.38 ; R249.2@1211.59,3050.2 1211.59,3039.37 1298.62,2952.34 L4.4@1310.33,2952.34 ; R248.2@1250.51,2881.41 1252.32,2883.23 1252.32,2888.08 1302.74,2938.5 L4.4@1302.74,2947.36
CAN0_CANH_R: L4.1 R248.1 U13.7 | length 179.4
  Top Layer w8: L4.1@1302.74,2768.23 1302.74,2759.37 1316.46,2745.65 1318.27,2745.65 1338.81,2725.11 U13.7@1338.81,2692.44
  Top Layer w20: R248.1@1250.51,2834.17 1250.51,2830.23 1295.03,2785.72 1295.03,2775.94 L4.1@1302.74,2768.23
CAN0_CANL: C221.2 D16.1 J5.4 J5.7 J21.2 L4.3 R252.1 R254.2 | length 1569.7
  Top Layer w20: J5.7@803.52,3653.54 807.3,3657.32 807.3,3720.84 822.84,3736.38 902.31,3736.38 917.85,3720.84 917.85,3657.32 925.41,3649.76 925.41,3584.55 937.13,3572.84 1264.31,3572.84 J21.2@1401.61,3435.53 1389.37,3423.3 1389.37,3345.98 1391.18,3344.17 1399.06,3344.17 1428.9,3314.33 1449.21,3314.33 C221.2@1457.91,3305.63 ; C221.2@1457.91,3304.64 1457.91,3303.66 1466.61,3294.96 1478.42,3294.96 1503.18,3270.19 1503.18,3055.71 R252.1@1508.7,3050.2 ; R254.2@1459.88,2881.41 1458.26,2881.41 1401.17,2938.5 1401.17,2956.22 1408.89,2963.93 1413.9,2963.93 1476.77,3026.8 1487.59,3026.8 R252.1@1503.18,3042.39
CAN0_CANL_R: L4.2 R254.1 U13.6 | length 182.8
  Top Layer w8: U13.6@1364.4,2692.44 1364.4,2722.6 1401.17,2759.37 L4.2@1401.17,2768.23 L4.2@1401.17,2777.08 ; R254.1@1459.88,2833.83 R254.1@1459.88,2834.17
  Top Layer w20: L4.2@1401.17,2777.08 1408.89,2784.8 1412.81,2784.8 1457.91,2829.9 R254.1@1457.91,2833.83
CAN0_RX: U8.7 U13.4 | length 392.9
  Top Layer w8: U8.7@1310.2,2421.91 1310.2,2398.29 1333.89,2374.6 1430.27,2374.6 1437.65,2381.98 1437.65,2532.6 1396.84,2573.41 1394.85,2573.41 1389.99,2578.26 U13.4@1389.99,2590.08
CAN0_STB: R255.1 R256.1 U13.8 | length 118.4
  Top Layer w8: R256.1@1206.74,2707.28 1298.38,2707.28 1298.54,2707.12 1308.36,2707.12 1313.22,2702.26 U13.8@1313.22,2692.44
CAN0_TX: U8.6 U13.1 | length 191.6
  Top Layer w8: U13.1@1313.22,2590.08 1308.36,2585.22 1308.36,2504.24 1352.39,2460.21 1352.39,2429.72 U8.6@1360.2,2421.91
CB0_A1: C93_A1.2 C103_A1.1 R84_A1.2 R85_A1.2 R86_A1.2 R87_A1.2 U1_A1.39 | length 1946.3
  Top Layer w10: v1(3178.03,1024.15) 3179.03,1025.15 3179.03,1081.64 U1_A1.39@3179.94,1082.55
  Bottom Layer w10: v1(3178.03,1024.15) 3178.03,1020.37 3216.47,981.93 3216.47,964.97 3223.28,958.16 C93_A1.2@3227.22,958.16 3227.22,915.84 C103_A1.1@3233.76,909.3
  Bottom Layer w12: R87_A1.2@2544.54,2033.6 2558.79,2019.34 2580.51,2019.34 2610.81,1989.04 2610.81,1784.13 2555.99,1729.31 2555.99,1338.22 2557.67,1336.53 2557.67,1234.74 2573.06,1219.35 2573.06,1213.93 2962.61,824.38 3053.33,824.38 3055.72,826.77 3147.29,826.77 3229.82,909.3 C103_A1.1@3233.76,909.3
  other v1: 2612.77,2014.09 2612.77,2047.28 2612.77,2080.46 2612.77,2113.65 2612.77,2146.83 2612.77,2180.02 2612.77,2213.2
CB0_A2: C93_A2.2 C103_A2.1 R84_A2.2 R85_A2.2 R86_A2.2 R87_A2.2 U1_A2.39 | length 1946.3
  Top Layer w10: v1(5473.05,1024.15) 5474.05,1025.15 5474.05,1081.64 U1_A2.39@5474.96,1082.55
  Bottom Layer w10: v1(5473.05,1024.15) 5473.05,1020.37 5511.48,981.93 5511.48,964.97 5518.29,958.16 C93_A2.2@5522.23,958.16 5522.23,915.84 C103_A2.1@5528.77,909.3
  Bottom Layer w12: R87_A2.2@4839.55,2033.6 4853.81,2019.34 4875.52,2019.34 4905.82,1989.04 4905.82,1784.13 4851,1729.31 4851,1338.22 4852.69,1336.53 4852.69,1234.74 4868.07,1219.35 4868.07,1213.93 5257.62,824.38 5348.35,824.38 5350.74,826.77 5442.31,826.77 5524.84,909.3 C103_A2.1@5528.77,909.3
  other v1: 4907.79,2014.09 4907.79,2047.28 4907.79,2080.46 4907.79,2113.65 4907.79,2146.83 4907.79,2180.02 4907.79,2213.2
CB0_A3: C93_A3.2 C103_A3.1 R84_A3.2 R85_A3.2 R86_A3.2 R87_A3.2 U1_A3.39 | length 1946.3
  Top Layer w10: v1(7809.64,1027.36) 7810.65,1028.36 7810.65,1084.85 U1_A3.39@7811.55,1085.75
  Bottom Layer w10: v1(7809.64,1027.36) 7809.64,1023.58 7848.08,985.14 7848.08,968.18 7854.89,961.37 C93_A3.2@7858.83,961.37 7858.83,919.05 C103_A3.1@7865.37,912.51
  Bottom Layer w12: R87_A3.2@7176.15,2036.8 7190.4,2022.55 7212.12,2022.55 7242.42,1992.25 7242.42,1787.33 7187.6,1732.52 7187.6,1341.42 7189.28,1339.74 7189.28,1237.95 7204.67,1222.56 7204.67,1217.14 7594.22,827.59 7684.94,827.59 7687.33,829.98 7778.9,829.98 7861.43,912.51 C103_A3.1@7865.37,912.51
  other v1: 7244.39,2017.3 7244.39,2050.49 7244.39,2083.67 7244.39,2116.86 7244.39,2150.04 7244.39,2183.23 7244.39,2216.41
CB0_A4: C93_A4.2 C103_A4.1 R84_A4.2 R85_A4.2 R86_A4.2 R87_A4.2 U1_A4.39 | length 1946.3
  Top Layer w10: v1(10129.87,1024.15) 10130.88,1025.15 10130.88,1081.64 U1_A4.39@10131.78,1082.55
  Bottom Layer w10: v1(10129.87,1024.15) 10129.87,1020.37 10168.31,981.93 10168.31,964.97 10175.12,958.16 C93_A4.2@10179.06,958.16 10179.06,915.84 C103_A4.1@10185.6,909.3
  Bottom Layer w12: R87_A4.2@9496.38,2033.6 9510.63,2019.34 9532.35,2019.34 9562.65,1989.04 9562.65,1784.13 9507.83,1729.31 9507.83,1338.22 9509.51,1336.53 9509.51,1234.74 9524.9,1219.35 9524.9,1213.93 9914.45,824.38 10005.17,824.38 10007.56,826.77 10099.13,826.77 10181.66,909.3 C103_A4.1@10185.6,909.3
  other v1: 9564.62,2014.09 9564.62,2047.28 9564.62,2080.46 9564.62,2113.65 9564.62,2146.83 9564.62,2180.02 9564.62,2213.2
CB1_A1: C72_A1.2 C93_A1.1 R69_A1.2 R72_A1.2 R76_A1.2 R80_A1.2 U1_A1.37 | length 2220.8
  Top Layer w10: v1(3129.66,1019.15) 3129.66,1022.39 3138.28,1031.01 3138.28,1044.01 3139.66,1045.4 3139.66,1081.64 U1_A1.37@3140.57,1082.55
  Bottom Layer w10: R76_A1.2@2541.39,2348.07 2540.76,2347.43 2540.76,2341.02 2549.66,2332.12 2549.66,2280.97 2555.51,2275.12 2633.29,2275.12 2641.2,2267.2 2641.53,2267.2 2649.44,2259.29 2649.44,2258.96 2651.45,2256.95 2651.45,1798.08 2574.86,1721.49 2574.86,1346.03 2576.54,1344.35 2576.54,1242.56 2591.93,1227.17 2591.93,1221.75 2970.42,843.26 3045.51,843.26 3047.9,845.65 3103.33,845.65 3149.49,891.8 3149.49,894.26 3169.22,914 3169.22,951.35 C93_A1.1@3176.03,958.16 ; v1(3129.66,1019.15) 3131.96,1016.85 3131.96,1002.23 C93_A1.1@3176.03,958.16 ; C93_A1.1@3179.97,958.16 C93_A1.1@3176.03,958.16
  other v1: 2602.93,2329.05 2602.93,2362.24 2602.93,2395.42 2602.93,2428.61 2602.93,2461.79 2602.93,2486.96
CB1_A2: C72_A2.2 C93_A2.1 R69_A2.2 R72_A2.2 R76_A2.2 R80_A2.2 U1_A2.37 | length 2220.8
  Top Layer w10: v1(5424.68,1019.15) 5424.68,1022.39 5433.29,1031.01 5433.29,1044.01 5434.68,1045.4 5434.68,1081.64 U1_A2.37@5435.59,1082.55
  Bottom Layer w10: R76_A2.2@4836.41,2348.07 4835.77,2347.43 4835.77,2341.02 4844.67,2332.12 4844.67,2280.97 4850.53,2275.12 4928.3,2275.12 4936.21,2267.2 4936.54,2267.2 4944.46,2259.29 4944.46,2258.96 4946.46,2256.95 4946.46,1798.08 4869.88,1721.49 4869.88,1346.03 4871.56,1344.35 4871.56,1242.56 4886.95,1227.17 4886.95,1221.75 5265.44,843.26 5340.53,843.26 5342.92,845.65 5398.34,845.65 5444.5,891.8 5444.5,894.26 5464.24,914 5464.24,951.35 C93_A2.1@5471.05,958.16 ; v1(5424.68,1019.15) 5426.98,1016.85 5426.98,1002.23 C93_A2.1@5471.05,958.16 ; C93_A2.1@5474.99,958.16 C93_A2.1@5471.05,958.16
  other v1: 4897.95,2329.05 4897.95,2362.24 4897.95,2395.42 4897.95,2428.61 4897.95,2461.79 4897.95,2486.96
CB1_A3: C72_A3.2 C93_A3.1 R69_A3.2 R72_A3.2 R76_A3.2 R80_A3.2 U1_A3.37 | length 2220.8
  Top Layer w10: v1(7761.28,1022.35) 7761.28,1025.6 7769.89,1034.22 7769.89,1047.22 7771.28,1048.6 7771.28,1084.85 U1_A3.37@7772.18,1085.75
  Bottom Layer w10: R76_A3.2@7173.01,2351.28 7172.37,2350.64 7172.37,2344.23 7181.27,2335.33 7181.27,2284.18 7187.13,2278.32 7264.9,2278.32 7272.81,2270.41 7273.14,2270.41 7281.05,2262.5 7281.05,2262.17 7283.06,2260.16 7283.06,1801.28 7206.47,1724.7 7206.47,1349.24 7208.16,1347.56 7208.16,1245.76 7223.54,1230.38 7223.54,1224.96 7602.04,846.47 7677.13,846.47 7679.52,848.85 7734.94,848.85 7781.1,895.01 7781.1,897.47 7800.84,917.21 7800.84,954.56 C93_A3.1@7807.65,961.37 ; v1(7761.28,1022.35) 7763.58,1020.06 7763.58,1005.44 C93_A3.1@7807.65,961.37 ; C93_A3.1@7811.58,961.37 C93_A3.1@7807.65,961.37
  other v1: 7234.54,2332.26 7234.54,2365.45 7234.54,2398.63 7234.54,2431.82 7234.54,2465 7234.54,2490.17
CB1_A4: C72_A4.2 C93_A4.1 R69_A4.2 R72_A4.2 R76_A4.2 R80_A4.2 U1_A4.37 | length 2220.8
  Top Layer w10: v1(10081.51,1019.15) 10081.51,1022.39 10090.12,1031.01 10090.12,1044.01 10091.51,1045.4 10091.51,1081.64 U1_A4.37@10092.41,1082.55
  Bottom Layer w10: R76_A4.2@9493.24,2348.07 9492.6,2347.43 9492.6,2341.02 9501.5,2332.12 9501.5,2280.97 9507.36,2275.12 9585.13,2275.12 9593.04,2267.2 9593.37,2267.2 9601.28,2259.29 9601.28,2258.96 9603.29,2256.95 9603.29,1798.08 9526.7,1721.49 9526.7,1346.03 9528.39,1344.35 9528.39,1242.56 9543.77,1227.17 9543.77,1221.75 9922.27,843.26 9997.36,843.26 9999.75,845.65 10055.17,845.65 10101.33,891.8 10101.33,894.26 10121.07,914 10121.07,951.35 C93_A4.1@10127.88,958.16 ; v1(10081.51,1019.15) 10083.81,1016.85 10083.81,1002.23 C93_A4.1@10127.88,958.16 ; C93_A4.1@10131.81,958.16 C93_A4.1@10127.88,958.16
  other v1: 9554.77,2329.05 9554.77,2362.24 9554.77,2395.42 9554.77,2428.61 9554.77,2461.79 9554.77,2486.96
CB2_A1: C52_A1.2 C72_A1.1 R55_A1.2 R58_A1.2 R62_A1.2 R66_A1.2 U1_A1.35 | length 2449.1
  Top Layer w10: v1(3070.42,1018.27) 3072.5,1018.27 3100.29,1046.06 3100.29,1081.64 U1_A1.35@3101.2,1082.55
  Bottom Layer w10: v1(3070.42,1018.27) 3104.05,984.64 3104.05,972.84 3118.73,958.16 C52_A1.2@3122.67,958.16 3120.86,956.36 C72_A1.1@3120.86,908.95
  Bottom Layer w12: R66_A1.2@2541.39,2664.29 2549.57,2656.12 2597.83,2656.12 2631.71,2622.23 2631.71,2584.26 2668.31,2547.66 2668.31,2266.78 2670.32,2264.77 2670.32,1790.26 2593.74,1713.67 2593.74,1353.85 2595.42,1352.17 2595.42,1250.37 2610.81,1234.99 2610.81,1229.57 2978.24,862.13 3037.7,862.13 3040.08,864.52 3072.5,864.52 3116.93,908.95 C72_A1.1@3120.86,908.95
  other v1: 2602.93,2644.02 2602.93,2677.2 2602.93,2710.38 2602.93,2743.57 2602.93,2776.75 2602.93,2809.94 2602.93,2843.12
CB2_A2: C52_A2.2 C72_A2.1 R55_A2.2 R58_A2.2 R62_A2.2 R66_A2.2 U1_A2.35 | length 2449.1
  Top Layer w10: v1(5365.43,1018.27) 5367.51,1018.27 5395.31,1046.06 5395.31,1081.64 U1_A2.35@5396.22,1082.55
  Bottom Layer w10: v1(5365.43,1018.27) 5399.06,984.64 5399.06,972.84 5413.75,958.16 C52_A2.2@5417.68,958.16 5415.88,956.36 C72_A2.1@5415.88,908.95
  Bottom Layer w12: R66_A2.2@4836.41,2664.29 4844.58,2656.12 4892.84,2656.12 4926.73,2622.23 4926.73,2584.26 4963.33,2547.66 4963.33,2266.78 4965.34,2264.77 4965.34,1790.26 4888.75,1713.67 4888.75,1353.85 4890.43,1352.17 4890.43,1250.37 4905.82,1234.99 4905.82,1229.57 5273.26,862.13 5332.71,862.13 5335.1,864.52 5367.52,864.52 5411.94,908.95 C72_A2.1@5415.88,908.95
  other v1: 4897.95,2644.02 4897.95,2677.2 4897.95,2710.38 4897.95,2743.57 4897.95,2776.75 4897.95,2809.94 4897.95,2843.12
CB2_A3: C52_A3.2 C72_A3.1 R55_A3.2 R58_A3.2 R62_A3.2 R66_A3.2 U1_A3.35 | length 2449.1
  Top Layer w10: v1(7702.03,1021.47) 7704.11,1021.47 7731.91,1049.27 7731.91,1084.85 U1_A3.35@7732.81,1085.75
  Bottom Layer w10: v1(7702.03,1021.47) 7735.66,987.85 7735.66,976.05 7750.34,961.37 C52_A3.2@7754.28,961.37 7752.48,959.56 C72_A3.1@7752.48,912.16
  Bottom Layer w12: R66_A3.2@7173.01,2667.5 7181.18,2659.32 7229.44,2659.32 7263.32,2625.44 7263.32,2587.47 7299.93,2550.87 7299.93,2269.99 7301.93,2267.98 7301.93,1793.47 7225.35,1716.88 7225.35,1357.06 7227.03,1355.38 7227.03,1253.58 7242.42,1238.19 7242.42,1232.78 7609.86,865.34 7669.31,865.34 7671.7,867.73 7704.11,867.73 7748.54,912.16 C72_A3.1@7752.48,912.16
  other v1: 7234.54,2647.22 7234.54,2680.41 7234.54,2713.59 7234.54,2746.78 7234.54,2779.96 7234.54,2813.15 7234.54,2846.33
CB2_A4: C52_A4.2 C72_A4.1 R55_A4.2 R58_A4.2 R62_A4.2 R66_A4.2 U1_A4.35 | length 2449.1
  Top Layer w10: v1(10022.26,1018.27) 10024.34,1018.27 10052.14,1046.06 10052.14,1081.64 U1_A4.35@10053.04,1082.55
  Bottom Layer w10: v1(10022.26,1018.27) 10055.89,984.64 10055.89,972.84 10070.57,958.16 C52_A4.2@10074.51,958.16 10072.71,956.36 C72_A4.1@10072.71,908.95
  Bottom Layer w12: R66_A4.2@9493.24,2664.29 9501.41,2656.12 9549.67,2656.12 9583.55,2622.23 9583.55,2584.26 9620.16,2547.66 9620.16,2266.78 9622.16,2264.77 9622.16,1790.26 9545.58,1713.67 9545.58,1353.85 9547.26,1352.17 9547.26,1250.37 9562.65,1234.99 9562.65,1229.57 9930.08,862.13 9989.54,862.13 9991.93,864.52 10024.34,864.52 10068.77,908.95 C72_A4.1@10072.71,908.95
  other v1: 9554.77,2644.02 9554.77,2677.2 9554.77,2710.38 9554.77,2743.57 9554.77,2776.75 9554.77,2809.94 9554.77,2843.12
CB3_A1: C34_A1.2 C52_A1.1 R42_A1.2 R45_A1.2 R48_A1.2 R52_A1.2 U1_A1.33 | length 2737.4
  Top Layer w12: v1@2986.97,1030.76 3038.76,1082.55 U1_A1.33@3061.74,1082.55
  Bottom Layer w12: R52_A1.2@2535.94,2980.51 2549.66,2966.8 2549.66,2925.23 2573.37,2901.52 2640.21,2901.52 2656.67,2885.05 2656.67,2587.41 2688.19,2555.89 2688.19,2275.01 2690.19,2273 2690.19,1782.03 2613.61,1705.44 2613.61,1362.08 2615.29,1360.4 2615.29,1258.61 2630.68,1243.22 2630.68,1237.8 2986.47,882 3029.46,882 3037.59,890.13 3037.59,894.01 3055.21,911.63 3055.21,937.95 3065.68,948.41 3065.68,952.35 C52_A1.1@3071.49,958.16 ; v1(2985.06,1022.22) 2986.97,1020.31 3009.34,1020.31 C52_A1.1@3071.49,958.16 ; C52_A1.1@3075.42,958.16 C52_A1.1@3071.49,958.16
  other v1: 2602.93,2958.98 2602.93,2992.16 2602.93,3025.35 2602.93,3058.53 2602.93,3091.71 2602.93,3124.9 2602.93,3158.08
CB3_A2: C34_A2.2 C52_A2.1 R42_A2.2 R45_A2.2 R48_A2.2 R52_A2.2 U1_A2.33 | length 2737.4
  Top Layer w12: v1@5281.99,1030.76 5333.78,1082.55 U1_A2.33@5356.85,1082.55
  Bottom Layer w12: R52_A2.2@4830.96,2980.51 4844.67,2966.8 4844.67,2925.23 4868.38,2901.52 4935.22,2901.52 4951.69,2885.05 4951.69,2587.41 4983.2,2555.89 4983.2,2275.01 4985.21,2273 4985.21,1782.03 4908.62,1705.44 4908.62,1362.08 4910.31,1360.4 4910.31,1258.61 4925.7,1243.22 4925.7,1237.8 5281.49,882 5324.48,882 5332.61,890.13 5332.61,894.01 5350.23,911.63 5350.23,937.95 5360.69,948.41 5360.69,952.35 C52_A2.1@5366.5,958.16 ; v1(5280.07,1022.22) 5281.99,1020.31 5304.35,1020.31 C52_A2.1@5366.5,958.16 ; C52_A2.1@5370.44,958.16 C52_A2.1@5366.5,958.16
  other v1: 4897.95,2958.98 4897.95,2992.16 4897.95,3025.35 4897.95,3058.53 4897.95,3091.71 4897.95,3124.9 4897.95,3158.08
CB3_A3: C34_A3.2 C52_A3.1 R42_A3.2 R45_A3.2 R48_A3.2 R52_A3.2 U1_A3.33 | length 2737.4
  Top Layer w12: v1@7618.59,1033.96 7670.38,1085.75 U1_A3.33@7693.35,1085.75
  Bottom Layer w12: R52_A3.2@7167.56,2983.72 7181.27,2970.01 7181.27,2928.44 7204.98,2904.73 7271.82,2904.73 7288.28,2888.26 7288.28,2590.62 7319.8,2559.1 7319.8,2278.22 7321.81,2276.21 7321.81,1785.23 7245.22,1708.65 7245.22,1365.29 7246.9,1363.61 7246.9,1261.81 7262.29,1246.43 7262.29,1241.01 7618.09,885.21 7661.08,885.21 7669.2,893.34 7669.2,897.21 7686.83,914.84 7686.83,941.16 7697.29,951.62 7697.29,955.56 C52_A3.1@7703.1,961.37 ; v1(7616.67,1025.43) 7618.59,1023.52 7640.95,1023.52 C52_A3.1@7703.1,961.37 ; C52_A3.1@7707.04,961.37 C52_A3.1@7703.1,961.37
  other v1: 7234.54,2962.18 7234.54,2995.37 7234.54,3028.55 7234.54,3061.74 7234.54,3094.92 7234.54,3128.11 7234.54,3161.29
CB3_A4: C34_A4.2 C52_A4.1 R42_A4.2 R45_A4.2 R48_A4.2 R52_A4.2 U1_A4.33 | length 2737.4
  Top Layer w12: v1@9938.82,1030.76 9990.61,1082.55 U1_A4.33@10013.58,1082.55
  Bottom Layer w12: R52_A4.2@9487.79,2980.51 9501.5,2966.8 9501.5,2925.23 9525.21,2901.52 9592.05,2901.52 9608.51,2885.05 9608.51,2587.41 9640.03,2555.89 9640.03,2275.01 9642.04,2273 9642.04,1782.03 9565.45,1705.44 9565.45,1362.08 9567.13,1360.4 9567.13,1258.61 9582.52,1243.22 9582.52,1237.8 9938.32,882.01 9981.31,882.01 9989.43,890.13 9989.43,894.01 10007.06,911.63 10007.06,937.95 10017.52,948.41 10017.52,952.35 C52_A4.1@10023.33,958.16 ; v1(9936.9,1022.22) 9938.82,1020.31 9961.18,1020.31 C52_A4.1@10023.33,958.16 ; C52_A4.1@10027.27,958.16 C52_A4.1@10023.33,958.16
  other v1: 9554.77,2958.98 9554.77,2992.16 9554.77,3025.35 9554.77,3058.53 9554.77,3091.71 9554.77,3124.9 9554.77,3158.08
CB4_A1: C15_A1.2 C34_A1.1 R27_A1.2 R30_A1.2 R33_A1.2 R38_A1.2 U1_A1.31 | length 1589.5
  Top Layer w10: v1@2893.84,1159.94 2933.18,1159.94 2951.34,1178.1 2984.15,1178.1 U1_A1.31@2985.06,1179
  Bottom Layer w10: C15_A1.2@2824.15,1122.43 2840.81,1139.09 2849.74,1139.09 2868.29,1157.64 2891.54,1157.64 v1@2893.84,1159.94 ; C15_A1.2@2826.12,1120.47 2826.12,1085.6 3004.03,907.69 C34_A1.1@3007.97,907.69
  Bottom Layer w12: C15_A1.2@2821.79,1120.47 2785.4,1120.47 2635.17,1270.7 2635.17,1368.63 2633.48,1370.32 2633.48,1697.21 2898.9,1962.63 R38_A1.2@2898.9,2025.93
  other v1: 2895.24,1159.94 2957.26,2004.25 2957.26,2037.44 2957.26,2070.62 2957.26,2103.81 2957.26,2136.99 2957.26,2170.17 2957.26,2203.36
CB4_A2: C15_A2.2 C34_A2.1 R27_A2.2 R30_A2.2 R33_A2.2 R38_A2.2 U1_A2.31 | length 1589.5
  Top Layer w10: v1@5188.85,1159.94 5228.19,1159.94 5246.36,1178.1 5279.17,1178.1 U1_A2.31@5280.07,1179
  Bottom Layer w10: C15_A2.2@5119.17,1122.43 5135.82,1139.09 5144.75,1139.09 5163.31,1157.64 5186.55,1157.64 v1@5188.85,1159.94 ; C15_A2.2@5121.14,1120.47 5121.14,1085.6 5299.05,907.69 C34_A2.1@5302.99,907.69
  Bottom Layer w12: C15_A2.2@5116.8,1120.47 5080.42,1120.47 4930.18,1270.7 4930.18,1368.63 4928.5,1370.32 4928.5,1697.21 5193.92,1962.63 R38_A2.2@5193.92,2025.93
  other v1: 5190.25,1159.94 5252.28,2004.25 5252.28,2037.44 5252.28,2070.62 5252.28,2103.81 5252.28,2136.99 5252.28,2170.17 5252.28,2203.36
